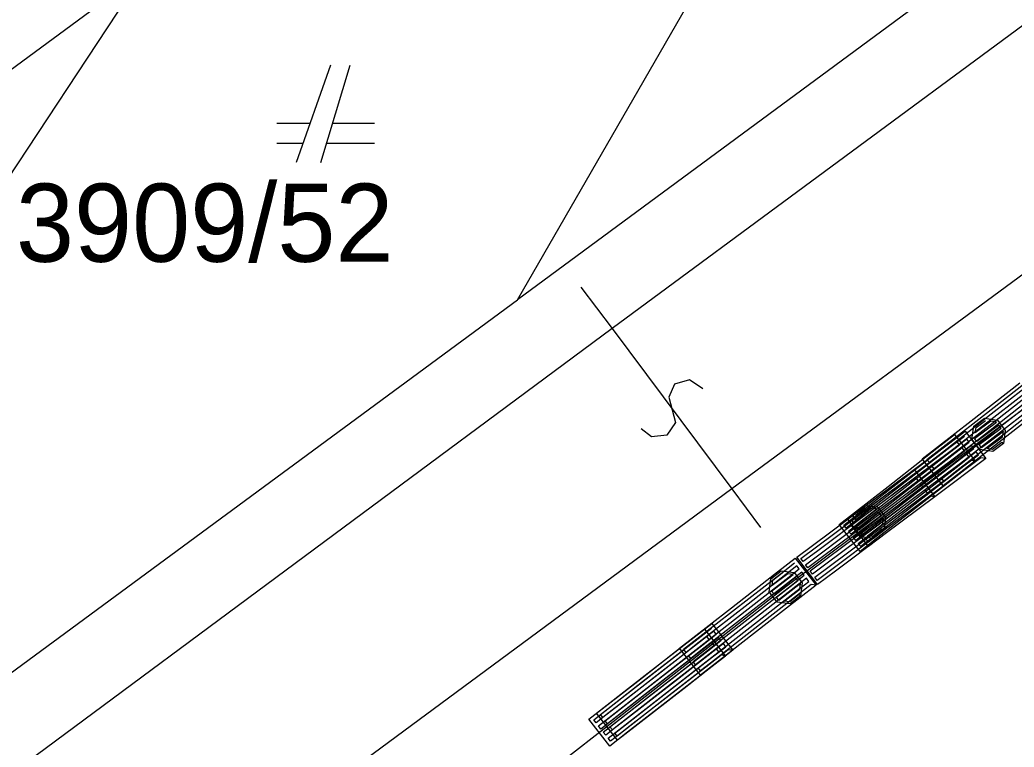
# Model space of a CAD drawing. Extents: x -266179 to -264727, y -1243225 to -1241702.
# Drawn here: x -265375.91 to -265355.55, y -1242960.59 to -1242945.7 of the extents above; entities that cross this region are included whole.
import ezdxf

# ---------------------------------------------------------------- set-up
doc = ezdxf.new("R2010")
doc.units = 0
for name, color, linetype in [('Vrstva 1', 7, 'Continuous'), ('Vrstva 19', 7, 'Continuous'), ('Vrstva 2', 7, 'Continuous'), ('Vrstva 21', 7, 'Continuous')]:
    doc.layers.add(name, color=color, linetype=linetype)

msp = doc.modelspace()

# ---------------------------------------------------------------- linework, layer by layer
at = {"layer": 'Vrstva 1'}
for p, q in [((-265365.72, -1242951.43), (-265358.53, -1242938.96)), ((-265355.76, -1242944.08), (-265365.72, -1242951.43)), ((-265402.32, -1242965.97), (-265373.36, -1242944.7)), ((-265373.36, -1242944.7), (-265382.4, -1242958.39)), ((-265369.55, -1242946.62), (-265370.25, -1242948.62)), ((-265369.75, -1242948.62), (-265369.15, -1242946.62)), ((-265369.97, -1242947.82), (-265370.65, -1242947.82)), ((-265368.65, -1242947.82), (-265369.51, -1242947.82)), ((-265370.65, -1242948.22), (-265370.11, -1242948.22)), ((-265369.63, -1242948.22), (-265368.65, -1242948.22)), ((-265350.86, -1242950.3), (-265360.22, -1242957.31)), ((-265381.63, -1242963.15), (-265365.72, -1242951.43)), ((-265360.22, -1242957.31), (-265363.64, -1242959.98)), ((-265363.64, -1242959.98), (-265365.35, -1242961.31))]:
    msp.add_line(p, q, dxfattribs=at)
at = {"layer": 'Vrstva 19'}
for p, q in [((-265350.86, -1242950.3), (-265360.22, -1242957.31)), ((-265360.22, -1242957.31), (-265363.64, -1242959.98)), ((-265363.64, -1242959.98), (-265365.35, -1242961.31))]:
    msp.add_line(p, q, dxfattribs=at)
for points in [[(-265355.012, -1242952.993), (-265356.014, -1242953.774), (-265357.015, -1242954.555), (-265357.283, -1242954.765), (-265357.332, -1242954.701), (-265356.331, -1242953.92), (-265355.33, -1242953.139)], [(-265354.635, -1242953.396), (-265355.636, -1242954.177), (-265356.637, -1242954.958), (-265357, -1242955.241), (-265357.431, -1242954.689), (-265356.429, -1242953.908), (-265355.428, -1242953.127)], [(-265354.914, -1242953.119), (-265355.915, -1242953.901), (-265356.917, -1242954.682), (-265357.185, -1242954.891), (-265357.234, -1242954.828), (-265356.233, -1242954.047), (-265355.231, -1242953.265)], [(-265354.816, -1242953.246), (-265355.817, -1242954.027), (-265356.818, -1242954.808), (-265357.086, -1242955.017), (-265357.136, -1242954.954), (-265356.134, -1242954.173), (-265355.133, -1242953.392)], [(-265354.717, -1242953.372), (-265355.719, -1242954.153), (-265356.72, -1242954.934), (-265356.988, -1242955.143), (-265357.037, -1242955.08), (-265356.036, -1242954.299), (-265355.034, -1242953.518)], [(-265355.767, -1242954.375), (-265355.983, -1242954.537), (-265356.249, -1242954.498), (-265356.411, -1242954.282), (-265356.372, -1242954.016), (-265356.156, -1242953.854), (-265355.89, -1242953.893), (-265355.729, -1242954.109), (-265355.767, -1242954.375), (-265355.799, -1242954.349), (-265355.991, -1242954.493), (-265356.103, -1242954.476), (-265355.783, -1242954.237), (-265355.767, -1242954.125), (-265356.215, -1242954.46), (-265356.263, -1242954.396), (-265355.815, -1242954.061), (-265355.862, -1242953.997), (-265356.311, -1242954.332), (-265356.359, -1242954.268), (-265355.91, -1242953.933), (-265356.022, -1242953.916), (-265356.343, -1242954.156), (-265356.327, -1242954.044), (-265356.134, -1242953.9)], [(-265356.129, -1242954.682), (-265357.146, -1242955.443), (-265358.162, -1242956.204), (-265358.531, -1242956.48), (-265358.95, -1242955.919), (-265357.933, -1242955.158), (-265356.916, -1242954.397), (-265356.548, -1242954.122), (-265356.129, -1242954.682), (-265356.227, -1242954.668), (-265357.244, -1242955.429), (-265358.26, -1242956.19), (-265358.533, -1242956.394), (-265358.581, -1242956.33), (-265357.564, -1242955.569), (-265356.547, -1242954.808), (-265356.275, -1242954.604), (-265356.323, -1242954.54), (-265357.339, -1242955.301), (-265358.356, -1242956.062), (-265358.628, -1242956.266), (-265358.676, -1242956.202), (-265357.66, -1242955.441), (-265356.643, -1242954.68), (-265356.37, -1242954.476), (-265356.418, -1242954.412), (-265357.435, -1242955.173), (-265358.452, -1242955.934), (-265358.724, -1242956.138), (-265358.772, -1242956.073), (-265357.755, -1242955.313), (-265356.739, -1242954.552), (-265356.466, -1242954.348), (-265356.514, -1242954.284), (-265357.531, -1242955.045), (-265358.548, -1242955.806), (-265358.82, -1242956.009), (-265358.868, -1242955.945), (-265357.851, -1242955.184), (-265356.834, -1242954.424), (-265356.562, -1242954.22)], [(-265356.335, -1242954.739), (-265357.337, -1242955.519), (-265358.339, -1242956.3), (-265358.702, -1242956.582), (-265359.132, -1242956.03), (-265358.13, -1242955.25), (-265357.128, -1242954.47), (-265356.765, -1242954.187), (-265356.335, -1242954.739), (-265356.417, -1242954.715), (-265357.419, -1242955.495), (-265358.422, -1242956.275), (-265358.69, -1242956.484), (-265358.739, -1242956.421), (-265357.737, -1242955.641), (-265356.735, -1242954.861), (-265356.466, -1242954.652), (-265356.516, -1242954.589), (-265357.518, -1242955.369), (-265358.52, -1242956.149), (-265358.788, -1242956.358), (-265358.837, -1242956.294), (-265357.835, -1242955.514), (-265356.833, -1242954.734), (-265356.565, -1242954.526), (-265356.614, -1242954.462), (-265357.616, -1242955.242), (-265358.618, -1242956.023), (-265358.886, -1242956.231), (-265358.936, -1242956.168), (-265357.933, -1242955.388), (-265356.931, -1242954.608), (-265356.663, -1242954.399), (-265356.712, -1242954.336), (-265357.714, -1242955.116), (-265358.716, -1242955.896), (-265358.985, -1242956.105), (-265359.034, -1242956.042), (-265358.032, -1242955.262), (-265357.03, -1242954.482), (-265356.761, -1242954.273)], [(-265357.174, -1242955.465), (-265358.191, -1242956.226), (-265359.208, -1242956.987), (-265359.576, -1242957.263), (-265359.995, -1242956.702), (-265358.979, -1242955.941), (-265357.962, -1242955.18), (-265357.593, -1242954.905), (-265357.174, -1242955.465), (-265357.272, -1242955.451), (-265358.289, -1242956.212), (-265359.306, -1242956.973), (-265359.578, -1242957.177), (-265359.626, -1242957.113), (-265358.609, -1242956.352), (-265357.592, -1242955.591), (-265357.32, -1242955.387), (-265357.368, -1242955.323), (-265358.385, -1242956.084), (-265359.402, -1242956.845), (-265359.674, -1242957.048), (-265359.722, -1242956.984), (-265358.705, -1242956.224), (-265357.688, -1242955.463), (-265357.416, -1242955.259), (-265357.464, -1242955.195), (-265358.481, -1242955.956), (-265359.497, -1242956.717), (-265359.77, -1242956.92), (-265359.818, -1242956.856), (-265358.801, -1242956.095), (-265357.784, -1242955.335), (-265357.512, -1242955.131), (-265357.56, -1242955.067), (-265358.576, -1242955.828), (-265359.593, -1242956.589), (-265359.866, -1242956.792), (-265359.913, -1242956.728), (-265358.897, -1242955.967), (-265357.88, -1242955.206), (-265357.608, -1242955.003)], [(-265358.217, -1242956.152), (-265358.43, -1242956.318), (-265358.697, -1242956.286), (-265358.863, -1242956.073), (-265358.83, -1242955.806), (-265358.617, -1242955.64), (-265358.35, -1242955.673), (-265358.184, -1242955.886), (-265358.217, -1242956.152), (-265358.25, -1242956.127), (-265358.439, -1242956.275), (-265358.551, -1242956.261), (-265358.236, -1242956.015), (-265358.222, -1242955.902), (-265358.663, -1242956.247), (-265358.713, -1242956.184), (-265358.271, -1242955.839), (-265358.32, -1242955.776), (-265358.762, -1242956.121), (-265358.811, -1242956.058), (-265358.369, -1242955.713), (-265358.482, -1242955.699), (-265358.797, -1242955.945), (-265358.783, -1242955.833), (-265358.594, -1242955.685)], [(-265359.602, -1242957.271), (-265360.604, -1242958.052), (-265361.605, -1242958.833), (-265361.968, -1242959.116), (-265362.398, -1242958.564), (-265361.397, -1242957.783), (-265360.395, -1242957.002), (-265360.033, -1242956.719), (-265359.602, -1242957.271), (-265359.701, -1242957.259), (-265360.702, -1242958.04), (-265361.703, -1242958.821), (-265361.971, -1242959.03), (-265362.021, -1242958.967), (-265361.019, -1242958.186), (-265360.018, -1242957.405), (-265359.75, -1242957.196), (-265359.799, -1242957.133), (-265360.8, -1242957.914), (-265361.802, -1242958.695), (-265362.07, -1242958.904), (-265362.119, -1242958.841), (-265361.118, -1242958.06), (-265360.116, -1242957.279), (-265359.848, -1242957.069), (-265359.897, -1242957.006), (-265360.899, -1242957.787), (-265361.9, -1242958.568), (-265362.168, -1242958.778), (-265362.217, -1242958.715), (-265361.216, -1242957.933), (-265360.215, -1242957.152), (-265359.947, -1242956.943), (-265359.996, -1242956.88), (-265360.997, -1242957.661), (-265361.999, -1242958.442), (-265362.267, -1242958.651), (-265362.316, -1242958.588), (-265361.314, -1242957.807), (-265360.313, -1242957.026), (-265360.045, -1242956.817)], [(-265359.92, -1242957.492), (-265360.133, -1242957.658), (-265360.4, -1242957.625), (-265360.566, -1242957.412), (-265360.532, -1242957.145), (-265360.319, -1242956.979), (-265360.053, -1242957.012), (-265359.887, -1242957.225), (-265359.92, -1242957.492), (-265359.953, -1242957.467), (-265360.142, -1242957.614), (-265360.254, -1242957.6), (-265359.939, -1242957.354), (-265359.925, -1242957.242), (-265360.366, -1242957.586), (-265360.416, -1242957.523), (-265359.974, -1242957.179), (-265360.023, -1242957.116), (-265360.465, -1242957.46), (-265360.514, -1242957.397), (-265360.072, -1242957.053), (-265360.184, -1242957.039), (-265360.5, -1242957.284), (-265360.486, -1242957.172), (-265360.296, -1242957.025)], [(-265361.462, -1242958.726), (-265362.463, -1242959.507), (-265363.465, -1242960.288), (-265363.827, -1242960.571), (-265364.258, -1242960.019), (-265363.256, -1242959.238), (-265362.255, -1242958.457), (-265361.892, -1242958.174), (-265361.462, -1242958.726), (-265361.544, -1242958.702), (-265362.546, -1242959.483), (-265363.547, -1242960.264), (-265363.815, -1242960.473), (-265363.864, -1242960.41), (-265362.863, -1242959.629), (-265361.861, -1242958.848), (-265361.593, -1242958.639), (-265361.643, -1242958.575), (-265362.644, -1242959.357), (-265363.645, -1242960.138), (-265363.913, -1242960.347), (-265363.963, -1242960.284), (-265362.961, -1242959.503), (-265361.96, -1242958.722), (-265361.692, -1242958.512), (-265361.741, -1242958.449), (-265362.742, -1242959.23), (-265363.744, -1242960.011), (-265364.012, -1242960.221), (-265364.061, -1242960.157), (-265363.06, -1242959.376), (-265362.058, -1242958.595), (-265361.79, -1242958.386), (-265361.839, -1242958.323), (-265362.841, -1242959.104), (-265363.842, -1242959.885), (-265364.11, -1242960.094), (-265364.159, -1242960.031), (-265363.158, -1242959.25), (-265362.157, -1242958.469), (-265361.889, -1242958.26)], [(-265361.306, -1242958.609), (-265362.308, -1242959.389), (-265363.311, -1242960.169), (-265363.674, -1242960.452), (-265364.104, -1242959.899), (-265363.101, -1242959.119), (-265362.099, -1242958.339), (-265361.736, -1242958.057), (-265361.306, -1242958.609), (-265361.405, -1242958.597), (-265362.407, -1242959.377), (-265363.409, -1242960.157), (-265363.677, -1242960.366), (-265363.726, -1242960.303), (-265362.724, -1242959.523), (-265361.722, -1242958.743), (-265361.454, -1242958.534), (-265361.503, -1242958.471), (-265362.505, -1242959.251), (-265363.507, -1242960.031), (-265363.775, -1242960.24), (-265363.825, -1242960.176), (-265362.822, -1242959.396), (-265361.82, -1242958.616), (-265361.552, -1242958.407), (-265361.601, -1242958.344), (-265362.603, -1242959.124), (-265363.605, -1242959.904), (-265363.874, -1242960.113), (-265363.923, -1242960.05), (-265362.921, -1242959.27), (-265361.919, -1242958.49), (-265361.65, -1242958.281), (-265361.699, -1242958.218), (-265362.702, -1242958.998), (-265363.704, -1242959.778), (-265363.972, -1242959.987), (-265364.021, -1242959.924), (-265363.019, -1242959.144), (-265362.017, -1242958.364), (-265361.748, -1242958.155)]]:
    msp.add_lwpolyline(points, dxfattribs=at)
at = {"layer": 'Vrstva 2'}
for p, q in [((-265347.58, -1242940.06), (-265363.78, -1242952.02)), ((-265345.08, -1242943.32), (-265361.33, -1242955.3)), ((-265364.42, -1242951.17), (-265363.78, -1242952.02)), ((-265363.78, -1242952.02), (-265379.9, -1242963.96)), ((-265363.78, -1242952.02), (-265361.33, -1242955.3)), ((-265361.33, -1242955.3), (-265377.43, -1242967.19)), ((-265361.33, -1242955.3), (-265360.74, -1242956.09))]:
    msp.add_line(p, q, dxfattribs=at)
msp.add_lwpolyline([(-265361.924, -1242953.251), (-265362.198, -1242953.069), (-265362.504, -1242953.16), (-265362.621, -1242953.422), (-265362.482, -1242953.942), (-265362.662, -1242954.202), (-265362.974, -1242954.235), (-265363.186, -1242954.069)], dxfattribs=at)
at = {"layer": 'Vrstva 21'}
for p, q in [((-265350.86, -1242950.3), (-265360.22, -1242957.31)), ((-265360.22, -1242957.31), (-265363.64, -1242959.98)), ((-265363.64, -1242959.98), (-265365.35, -1242961.31))]:
    msp.add_line(p, q, dxfattribs=at)

# ---------------------------------------------------------------- texts
at = {"layer": 'Vrstva 1'}
msp.add_text('3909/52', height=1.6, dxfattribs=at).set_placement((-265375.993, -1242950.65))

doc.saveas('drawing.dxf')
